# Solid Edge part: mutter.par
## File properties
Title: mutter
Author: Stella-Marii
Template: iso metric part.par
Last saved by: Stella-Marii
Revision: 7
Application: Solid Edge
Density: 7833,000 kg/m^3
Accuracy: 0,990
Username: Stella-Marii
Document Number: 27
Material: Steel, structural
Face Style: Steel
Fill Style: ANSI32(Steel)
Virtual Style: Brushed steel
Grouping: Metals\Steel
LibraryName: Materials
Coef. of Thermal Exp: 1.3e-05
Thermal Conductivity: 32.0
Specific Heat: 481.0
Modulus of Elasticity: 199947953000.0
Poisson's Ratio: 0.29
Yield Stress: 262000766.0
Ultimate Stress: 358527364.0
Elongation: 0.0
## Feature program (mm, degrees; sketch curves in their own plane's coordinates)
sketch for "unnamed Protrusion 1" plane through (0, 0, 0) normal (0, 0, 1) x-axis (1, 0, 0)
  circle centre (0, 0) radius 5
extrude "unnamed Protrusion 1" add finite 60 along +normal
sketch for "unnamed RevolvedProtrusion 1" plane through (0, 0, 0) normal (0, 1, 0) x-axis (-1, 0, 0)
  arc centre (-0.0028, 0.5534) radius 6.8028 from (6.8, 0.5534) to (0, 7.3562) ccw
  line (6.8, 0) -> (6.8, 0.5534)
  line (0, 0) -> (6.8, 0)
  dimension (linear) = 6.8
revolve "unnamed RevolvedProtrusion 1" add full turn 360 deg about sketch line (0, 0) -> (0, 7.3562)
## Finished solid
Body 1: solid body, 3 faces, 2 edges, 1 vertex.
  Faces by surface: cylinder 1, plane 1, torus 1
  Edges by curve: circle 2
Bounding box of the edges (mm; curved faces can reach further): 13.600 x 13.600 x 0.553, from (-6.8, -6.8, 0) to (6.8, 6.8, 0.5534).
Cylindrical faces by radius (mm): R6.8 x1
Toroidal faces (ring radius, tube radius in mm): R-0.0028 r6.8028 x1
Planar faces by outward normal: -z 1
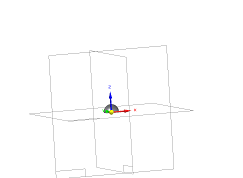
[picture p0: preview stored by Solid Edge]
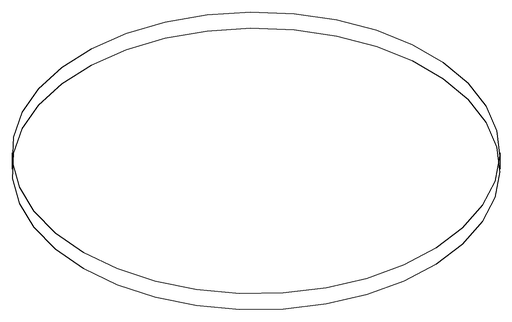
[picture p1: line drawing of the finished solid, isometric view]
